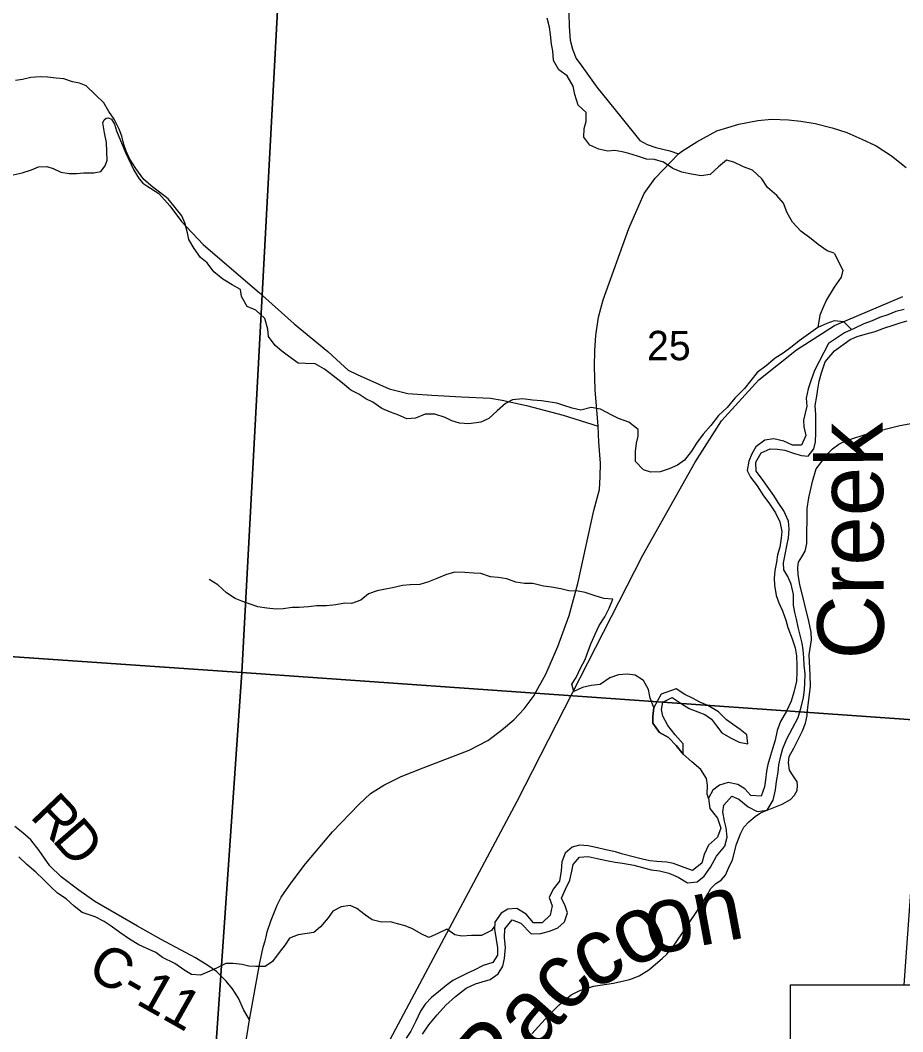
# Model space of a CAD drawing. Extents: x 0 to 34, y 0 to 22.
# Drawn here: x 27.504 to 28.762, y 18.393 to 19.835 of the extents above; entities that cross this region are included whole.
import ezdxf

# ---------------------------------------------------------------- set-up
doc = ezdxf.new("R2010")
doc.units = 0
for name, color, linetype in [('GM_X_County_Road', 7, 'Continuous'), ('GM_X_County_Road_Text', 7, 'Continuous'), ('GM_X_Major_River', 7, 'Continuous'), ('GM_X_Major_River_Text', 7, 'Continuous'), ('GM_X_Minor_Lake', 7, 'Continuous'), ('GM_X_Minor_River', 7, 'Continuous'), ('GM_X_Rail_Line', 7, 'Continuous'), ('GM_X_Section', 7, 'Continuous'), ('GM_X_Section_Text', 7, 'Continuous'), ('GM_X_State_Route', 7, 'Continuous'), ('GM_X_Township_Road', 7, 'Continuous'), ('SH_Data', 7, 'Continuous')]:
    doc.layers.add(name, color=color, linetype=linetype)

msp = doc.modelspace()

# ---------------------------------------------------------------- linework, layer by layer
at = {"layer": 'GM_X_County_Road'}
msp.add_lwpolyline([(27.831, 18.4095), (27.8225, 18.4242), (27.8154, 18.4407), (27.8069, 18.4538), (27.798, 18.4648), (27.7842, 18.4786), (27.772, 18.4872), (27.7543, 18.4979), (27.7053, 18.5242), (27.6717, 18.5432), (27.6108, 18.5786), (27.5882, 18.5945), (27.5628, 18.6135), (27.5466, 18.6294), (27.5316, 18.6511), (27.5197, 18.6661), (27.5083, 18.6765), (27.4967, 18.6851)], dxfattribs=at)
at = {"layer": 'GM_X_Major_River'}
for points in [[(28.7645, 19.4226), (28.7523, 19.4196), (28.741, 19.415), (28.7292, 19.4109), (28.7186, 19.4063), (28.7068, 19.4018), (28.6928, 19.3953), (28.6791, 19.3889), (28.6648, 19.3794)], [(28.6648, 19.3636), (28.6874, 19.3798), (28.6973, 19.384), (28.7087, 19.387), (28.7231, 19.3908), (28.7353, 19.3957), (28.7485, 19.4002), (28.7584, 19.4033), (28.7687, 19.4063)], [(28.6648, 19.3794), (28.6564, 19.3737), (28.6499, 19.3613), (28.643, 19.3484), (28.6365, 19.3352), (28.6314, 19.3208), (28.6276, 19.3091), (28.6248, 19.2958), (28.6255, 19.2844), (28.6232, 19.2746), (28.6208, 19.2644), (28.6215, 19.2549), (28.6241, 19.2427), (28.6179, 19.2291), (28.605, 19.2288), (28.5929, 19.2346), (28.5785, 19.2381), (28.5656, 19.236), (28.553, 19.2266), (28.5473, 19.2167), (28.543, 19.2062), (28.5407, 19.1929), (28.5452, 19.1834), (28.5546, 19.1712), (28.564, 19.1567), (28.5715, 19.1468), (28.5809, 19.1327), (28.5872, 19.1197), (28.5898, 19.106), (28.589, 19.0962), (28.587, 19.0837), (28.5839, 19.0727), (28.5823, 19.0621), (28.5799, 19.0504), (28.5791, 19.0394), (28.5794, 19.0295), (28.582, 19.0147), (28.5857, 19.0044), (28.5909, 18.9926), (28.5958, 18.9793), (28.5987, 18.969), (28.6047, 18.9531), (28.6088, 18.9401), (28.611, 18.9287), (28.6113, 18.9155), (28.6112, 18.9056), (28.6108, 18.8923), (28.6069, 18.8768), (28.603, 18.8639), (28.5964, 18.8496), (28.588, 18.8352), (28.5834, 18.822), (28.5802, 18.8083), (28.5767, 18.7962), (28.574, 18.7864), (28.5701, 18.7735), (28.5682, 18.764), (28.5666, 18.7519), (28.5654, 18.7417), (28.5604, 18.7284), (28.5456, 18.7293), (28.5373, 18.7392), (28.5271, 18.7454), (28.5135, 18.7481), (28.5013, 18.7444), (28.4918, 18.7369), (28.4856, 18.7256), (28.4874, 18.7111), (28.4983, 18.6974), (28.5028, 18.6829), (28.4981, 18.6701), (28.4852, 18.6588), (28.479, 18.6456), (28.4759, 18.6331), (28.4626, 18.6225), (28.4508, 18.6268), (28.4353, 18.6326), (28.4258, 18.6346), (28.4118, 18.6354), (28.4016, 18.6366), (28.3914, 18.6386), (28.3781, 18.6421), (28.3633, 18.646), (28.3527, 18.6491), (28.3391, 18.6519), (28.3274, 18.655), (28.3141, 18.6578), (28.3016, 18.6586), (28.2913, 18.656), (28.281, 18.6474), (28.2764, 18.6349), (28.2752, 18.622), (28.2732, 18.6076), (28.264, 18.5959), (28.2582, 18.5842), (28.2627, 18.572), (28.2596, 18.5588), (28.2485, 18.5479), (28.236, 18.548), (28.2255, 18.5605), (28.2122, 18.5686)], [(28.2057, 18.5523), (28.2178, 18.5473), (28.2329, 18.5324), (28.2465, 18.5327), (28.2602, 18.5364), (28.2705, 18.5409), (28.28, 18.5495), (28.2843, 18.5624), (28.2809, 18.5723), (28.2757, 18.5833), (28.2815, 18.5962), (28.288, 18.609), (28.2907, 18.6215), (28.2927, 18.631), (28.3015, 18.6416), (28.314, 18.6426), (28.3265, 18.6395), (28.3401, 18.6367), (28.3526, 18.6344), (28.3629, 18.6331), (28.3788, 18.6304), (28.3913, 18.6269), (28.4038, 18.6237), (28.4155, 18.6221), (28.4288, 18.6186), (28.442, 18.6132), (28.4556, 18.6051), (28.4693, 18.6066), (28.4792, 18.6144), (28.4884, 18.6273), (28.4968, 18.6428), (28.5087, 18.6571), (28.5122, 18.67), (28.5104, 18.6833), (28.5082, 18.6931), (28.5056, 18.7064), (28.5072, 18.7159), (28.5186, 18.7287), (28.5285, 18.7245), (28.5421, 18.7134), (28.5549, 18.7068), (28.569, 18.7086), (28.5774, 18.723), (28.5809, 18.7378), (28.5825, 18.7495), (28.5845, 18.7628), (28.5857, 18.7734), (28.5884, 18.7863), (28.5912, 18.7965), (28.5969, 18.8105), (28.6131, 18.8407), (28.6177, 18.8555), (28.6208, 18.8691), (28.6221, 18.8801), (28.6225, 18.8896), (28.623, 18.9028), (28.6219, 18.9154), (28.6212, 18.926), (28.6202, 18.937), (28.6187, 18.9465), (28.6161, 18.9579), (28.6132, 18.9697), (28.6106, 18.9811), (28.6084, 18.9906), (28.6065, 19.0008), (28.6066, 19.016), (28.6033, 19.0308), (28.5985, 19.0419), (28.5928, 19.0514), (28.5922, 19.0613), (28.5949, 19.073), (28.5972, 19.0855), (28.5996, 19.0969), (28.6004, 19.1094), (28.5994, 19.1204), (28.593, 19.1352), (28.5848, 19.1474), (28.5784, 19.1573), (28.5716, 19.1673), (28.5611, 19.1817), (28.5532, 19.192), (28.5529, 19.2046), (28.5606, 19.2182), (28.5735, 19.2238), (28.5837, 19.2233), (28.5944, 19.2217), (28.608, 19.2171), (28.6178, 19.2143), (28.6273, 19.2135), (28.6357, 19.2237), (28.6377, 19.2339), (28.6385, 19.2464), (28.6386, 19.2604), (28.6383, 19.2726), (28.6376, 19.2855), (28.6396, 19.2988), (28.6412, 19.309), (28.6432, 19.32), (28.6463, 19.3321), (28.6517, 19.348), (28.6648, 19.3636)], [(28.2122, 18.5686), (28.1993, 18.5676), (28.1898, 18.5619), (28.181, 18.5491), (28.1802, 18.5389), (28.1827, 18.5241), (28.1846, 18.5123), (28.1845, 18.502), (28.178, 18.4915), (28.1643, 18.487), (28.1513, 18.4803), (28.1418, 18.4762), (28.1316, 18.4709), (28.1209, 18.4657), (28.1114, 18.4586), (28.1007, 18.4495), (28.0908, 18.4417), (28.0816, 18.4319), (28.0751, 18.422), (28.0682, 18.4077), (28.0613, 18.3933), (28.0547, 18.3835)], [(28.0779, 18.3894), (28.0867, 18.4026), (28.0986, 18.4169), (28.1112, 18.4305), (28.1249, 18.4429), (28.1402, 18.4546), (28.1531, 18.4609), (28.1626, 18.4639), (28.1744, 18.4672), (28.1854, 18.4751), (28.1923, 18.4861), (28.1947, 18.497), (28.1959, 18.513), (28.1945, 18.5266), (28.195, 18.5395), (28.2057, 18.5523)]]:
    msp.add_lwpolyline(points, dxfattribs=at)
at = {"layer": 'GM_X_Minor_Lake'}
for points in [[(28.4495, 18.7883), (28.4491, 18.8031), (28.4381, 18.816), (28.4275, 18.8292), (28.4202, 18.8425), (28.4183, 18.8519), (28.4202, 18.8626), (28.4334, 18.8694), (28.4478, 18.8596), (28.458, 18.8535), (28.4702, 18.8487), (28.48, 18.8449), (28.4899, 18.8385), (28.4967, 18.8286), (28.5043, 18.8188), (28.5169, 18.8116), (28.529, 18.8056), (28.5415, 18.8033), (28.5399, 18.8158), (28.5304, 18.8238), (28.521, 18.8302), (28.5111, 18.8374), (28.4997, 18.8487), (28.4845, 18.8578), (28.4732, 18.8627), (28.4637, 18.868), (28.4519, 18.8736), (28.4394, 18.8816), (28.4181, 18.8742), (28.4077, 18.8549)], [(28.4077, 18.8549), (28.4062, 18.842), (28.4063, 18.8326), (28.4158, 18.8193), (28.4283, 18.8122), (28.4393, 18.8008), (28.4495, 18.7883)]]:
    msp.add_lwpolyline(points, dxfattribs=at)
at = {"layer": 'GM_X_Minor_River'}
for points in [[(28.6646, 19.5027), (28.6543, 19.5061), (28.6418, 19.5152), (28.6315, 19.5231), (28.6171, 19.534), (28.6053, 19.5469), (28.5977, 19.5602), (28.5924, 19.5738), (28.5829, 19.5851), (28.5696, 19.5961), (28.5612, 19.6086), (28.5483, 19.6211), (28.5351, 19.6256), (28.5214, 19.6324), (28.5112, 19.6354), (28.4995, 19.6259), (28.4878, 19.6149), (28.4749, 19.6129), (28.4613, 19.6152), (28.4473, 19.6182), (28.4348, 19.6234), (28.4211, 19.6325), (28.4086, 19.6363), (28.3972, 19.6366), (28.3844, 19.6408), (28.3718, 19.6449), (28.3624, 19.6471), (28.3518, 19.649), (28.3419, 19.6479), (28.3291, 19.6509), (28.3165, 19.6569), (28.3078, 19.6679), (28.3081, 19.6804), (28.3111, 19.6906), (28.3111, 19.7031), (28.2997, 19.7137), (28.2951, 19.7289), (28.2924, 19.741), (28.2841, 19.7557), (28.2723, 19.7641), (28.2647, 19.7773), (28.2635, 19.7913), (28.2616, 19.8008), (28.26, 19.8144), (28.2588, 19.825), (28.2554, 19.8379)], [(27.6236, 19.717), (27.6119, 19.7283), (27.5986, 19.7412), (27.5891, 19.7449), (27.5792, 19.7472), (27.5664, 19.7513), (27.5558, 19.7521), (27.5433, 19.7535), (27.5327, 19.7543), (27.5198, 19.7531), (27.5077, 19.7504), (27.4975, 19.7489)], [(28.6647, 19.4064), (28.6539, 19.4026), (28.641, 19.3969), (28.6146, 19.3779), (28.6048, 19.3695), (28.5919, 19.36), (28.5806, 19.3528), (28.5678, 19.3421), (28.5549, 19.3326), (28.5368, 19.3098), (28.5229, 19.2958), (28.5119, 19.2828), (28.4995, 19.2714), (28.4889, 19.257), (28.4776, 19.2445), (28.4682, 19.2319), (28.461, 19.2202), (28.4512, 19.2076), (28.4414, 19.2004), (28.4293, 19.1954), (28.4165, 19.1909), (28.4032, 19.1905), (28.393, 19.1938), (28.3816, 19.2056), (28.3812, 19.22), (28.383, 19.2317), (28.3852, 19.242), (28.3852, 19.2514), (28.3719, 19.262), (28.3572, 19.2669), (28.3477, 19.2718), (28.3314, 19.2805), (28.3181, 19.2827), (28.3034, 19.2789), (28.2912, 19.2815), (28.2791, 19.2853), (28.2693, 19.2887), (28.2568, 19.2906), (28.2473, 19.2924), (28.2348, 19.2932), (28.2208, 19.295), (28.206, 19.2938), (28.1962, 19.2885), (28.1841, 19.2779), (28.1724, 19.2668), (28.1607, 19.2619), (28.1437, 19.2596), (28.1304, 19.2603), (28.1198, 19.2637), (28.11, 19.2682), (28.0952, 19.2731), (28.0816, 19.2731), (28.068, 19.2673), (28.0555, 19.2666), (28.0426, 19.2722), (28.0323, 19.276), (28.0198, 19.2813), (28.0069, 19.2903), (27.9971, 19.2948), (27.9872, 19.3016), (27.9755, 19.3073), (27.9637, 19.3175), (27.9504, 19.3277), (27.9379, 19.3372), (27.925, 19.3451), (27.911, 19.3454), (27.9004, 19.3458), (27.8867, 19.356), (27.8772, 19.3632), (27.8677, 19.3711), (27.8582, 19.384), (27.8575, 19.3942), (27.8529, 19.4094), (27.8403, 19.4215), (27.8278, 19.4267), (27.8198, 19.4411), (27.8183, 19.451), (27.8065, 19.4574), (27.7933, 19.4657), (27.7804, 19.4763), (27.7708, 19.4888), (27.7614, 19.4967), (27.7522, 19.5092), (27.745, 19.5224), (27.7431, 19.5319), (27.7389, 19.5459), (27.7347, 19.5558), (27.7252, 19.5679), (27.7153, 19.58), (27.7031, 19.5898), (27.6933, 19.5966), (27.6804, 19.6079), (27.6693, 19.6235), (27.6606, 19.6367), (27.6553, 19.6481), (27.6522, 19.6575), (27.6491, 19.6697), (27.6457, 19.6795), (27.6385, 19.6939), (27.6309, 19.7049), (27.6236, 19.717)], [(28.6646, 19.5027), (28.677, 19.4785), (28.6743, 19.4683), (28.6647, 19.454)], [(28.6647, 19.454), (28.6535, 19.4364), (28.6494, 19.4266), (28.6441, 19.4144), (28.641, 19.3969)], [(28.6894, 19.3938), (28.6785, 19.4046), (28.6647, 19.4064)], [(28.4858, 18.7242), (28.4834, 18.7315), (28.4838, 18.7444), (28.4826, 18.7539), (28.4746, 18.7668), (28.4617, 18.7774), (28.4495, 18.7883), (28.4393, 18.8008), (28.4283, 18.8122), (28.4158, 18.8193), (28.4063, 18.8326), (28.4062, 18.842), (28.4077, 18.8549), (28.4024, 18.8682), (28.3997, 18.8807), (28.3928, 18.8936), (28.3807, 18.9011), (28.3693, 18.9026), (28.3572, 18.9015), (28.3447, 18.8973), (28.3311, 18.8877), (28.3183, 18.8862), (28.3058, 18.8835), (28.2937, 18.8778), (28.2906, 18.8884), (28.297, 18.8979), (28.303, 18.9112), (28.3094, 18.9233), (28.3143, 18.9366), (28.3184, 18.9469), (28.3241, 18.9594), (28.3297, 18.9719), (28.3376, 18.9841), (28.344, 18.9966), (28.3489, 19.0095), (28.336, 19.0106), (28.3239, 19.0144), (28.3095, 19.0189), (28.2997, 19.0207), (28.2864, 19.0211), (28.275, 19.0241), (28.2618, 19.0263), (28.2504, 19.0278), (28.2349, 19.0316), (28.2232, 19.0319), (28.211, 19.0338), (28.1981, 19.0383), (28.1856, 19.0402), (28.1747, 19.0413), (28.161, 19.0458), (28.1508, 19.0465), (28.1379, 19.0476), (28.1239, 19.048), (28.1122, 19.0445), (28.0982, 19.0388), (28.0865, 19.0342), (28.074, 19.0304), (28.06, 19.03), (28.0494, 19.0288), (28.035, 19.0258), (28.0252, 19.0235), (28.0131, 19.0212), (28.001, 19.017), (27.9897, 19.0082), (27.9768, 19.0033), (27.967, 19.0036), (27.9541, 19.0013), (27.9409, 19.0001), (27.9269, 18.9997), (27.9155, 18.9986), (27.9019, 18.9974), (27.892, 18.9974), (27.8792, 18.9958), (27.8693, 18.995), (27.8561, 18.9965), (27.8432, 18.9984), (27.8337, 19.0018), (27.8205, 19.0067), (27.8106, 19.0104), (27.7985, 19.0184), (27.7863, 19.0297), (27.7738, 19.0373)], [(28.1805, 18.5434), (28.1763, 18.537), (28.1619, 18.5298), (28.1476, 18.5301), (28.1339, 18.529), (28.1241, 18.5308), (28.1123, 18.5391), (28.0998, 18.533), (28.087, 18.5273), (28.076, 18.5322), (28.0635, 18.5394), (28.0533, 18.5439), (28.0423, 18.5465), (28.0324, 18.5496), (28.0192, 18.5491), (28.0059, 18.5521), (27.9964, 18.5589), (27.9843, 18.5684), (27.9748, 18.5725), (27.9619, 18.5706), (27.9502, 18.5645), (27.9434, 18.555), (27.9325, 18.5425), (27.9227, 18.5341), (27.9007, 18.531), (27.8883, 18.5261), (27.8819, 18.5166), (27.8736, 18.5056), (27.8641, 18.4927), (27.8536, 18.4858), (27.8403, 18.4858), (27.8305, 18.4861), (27.8206, 18.4888), (27.8078, 18.4899), (27.7975, 18.4902), (27.7851, 18.4837), (27.7749, 18.4792), (27.7616, 18.4734), (27.7484, 18.4742), (27.7389, 18.4802), (27.7249, 18.49), (27.7074, 18.4987), (27.6979, 18.5055), (27.6839, 18.5119), (27.6737, 18.5168), (27.6604, 18.5248), (27.6464, 18.5342), (27.6342, 18.5433), (27.6243, 18.5501), (27.6115, 18.5565), (27.5929, 18.5629), (27.5815, 18.5716), (27.5697, 18.5822), (27.5576, 18.5901), (27.5477, 18.5996), (27.5378, 18.6098), (27.5265, 18.6204), (27.5139, 18.6313), (27.5025, 18.6419)]]:
    msp.add_lwpolyline(points, dxfattribs=at)
at = {"layer": 'GM_X_Rail_Line'}
msp.add_lwpolyline([(27.978, 18.2807), (28.2126, 18.7214), (28.3919, 19.0722), (28.4664, 19.2048), (28.5039, 19.2636), (28.5573, 19.3219), (28.611, 19.3651), (28.6648, 19.3994), (28.7625, 19.4407)], dxfattribs=at)
at = {"layer": 'GM_X_Section'}
for points in [[(27.875, 19.9199), (27.8204, 18.905), (26.8274, 18.9732), (26.893, 19.9764)], [(27.875, 19.9199), (28.8721, 19.8598), (28.7909, 18.8364), (27.8204, 18.905)], [(26.8274, 18.9732), (27.8204, 18.905), (27.7492, 17.8771), (26.7513, 17.9427)]]:
    msp.add_lwpolyline(points, close=True, dxfattribs=at)
msp.add_lwpolyline([(28.7433, 18.1795), (28.7165, 17.8103), (27.7492, 17.8771), (27.8204, 18.905), (28.7909, 18.8364), (28.7636, 18.4595)], dxfattribs=at)
at = {"layer": 'GM_X_State_Route'}
for points in [[(28.3281, 19.2562), (28.3241, 19.3079), (28.3229, 19.3409), (28.3235, 19.3641), (28.3247, 19.3852), (28.3287, 19.4115), (28.3354, 19.436), (28.3718, 19.5379), (28.3868, 19.5715), (28.3935, 19.588), (28.4092, 19.6097), (28.4425, 19.6444), (28.4484, 19.6485), (28.4686, 19.6613), (28.4975, 19.677), (28.5284, 19.6868), (28.5557, 19.6917), (28.5752, 19.6936), (28.5994, 19.6929), (28.6168, 19.6908), (28.6376, 19.6877), (28.6618, 19.6816), (28.6826, 19.6746), (28.704, 19.6654), (28.7242, 19.6556), (28.7462, 19.6413), (28.7673, 19.625)], [(27.8167, 18.318), (27.831, 18.4095), (27.846, 18.4909), (27.8509, 18.5132), (27.8534, 18.5221), (27.8549, 18.5279), (27.8564, 18.5352), (27.8619, 18.552), (27.8708, 18.5731), (27.8763, 18.5845), (27.8904, 18.6052), (27.9109, 18.6322), (27.9495, 18.6777), (27.987, 18.7169), (28.0039, 18.7322), (28.0226, 18.7443), (28.0473, 18.7567), (28.0788, 18.7689), (28.1443, 18.794), (28.1709, 18.808), (28.1904, 18.8227), (28.2079, 18.8374), (28.2226, 18.8533), (28.2369, 18.8723), (28.2375, 18.8734), (28.2535, 18.9026), (28.2706, 18.942), (28.2868, 18.9861), (28.2993, 19.0316), (28.322, 19.1359), (28.3302, 19.1659), (28.3312, 19.1837), (28.3315, 19.2035), (28.3293, 19.2332), (28.3281, 19.2562)]]:
    msp.add_lwpolyline(points, dxfattribs=at)
at = {"layer": 'GM_X_Township_Road'}
for points in [[(28.2862, 19.845), (28.2868, 19.826), (28.2883, 19.8064), (28.2917, 19.7936), (28.297, 19.7802), (28.305, 19.7691), (28.3263, 19.7394), (28.3605, 19.6969), (28.3877, 19.6633), (28.3981, 19.6575), (28.4104, 19.6535), (28.4303, 19.6486), (28.4425, 19.6444)], [(27.4943, 19.6146), (27.5071, 19.6171), (27.5206, 19.6217), (27.5307, 19.6256), (27.5423, 19.6263), (27.5512, 19.6235), (27.5625, 19.6183), (27.5741, 19.6165), (27.5845, 19.6165), (27.5949, 19.6171), (27.6096, 19.6174), (27.6195, 19.619), (27.6255, 19.6272), (27.6285, 19.6351), (27.6273, 19.6605), (27.6246, 19.6743), (27.6224, 19.6887), (27.6243, 19.693), (27.6268, 19.6951), (27.6305, 19.6957), (27.6344, 19.6936), (27.6386, 19.6868), (27.6417, 19.677), (27.6546, 19.6461), (27.6662, 19.6208), (27.6738, 19.6085), (27.679, 19.6027), (27.6851, 19.5987), (27.702, 19.5877), (27.7179, 19.5703), (27.7344, 19.5477), (27.765, 19.5152), (27.8454, 19.4461), (27.895, 19.4021), (27.9427, 19.3626), (27.9607, 19.3461), (27.9717, 19.336), (27.9846, 19.3296), (28.0302, 19.3094), (28.0568, 19.3026), (28.091, 19.3002), (28.1336, 19.2981), (28.1748, 19.2959), (28.1911, 19.2932), (28.2259, 19.2855), (28.2785, 19.2718), (28.3281, 19.2562)], [(28.3729, 18.4674), (28.3756, 18.468), (28.3867, 18.4725), (28.4002, 18.4809), (28.4192, 18.4972), (28.4262, 18.5035), (28.4355, 18.5147), (28.4532, 18.5407), (28.4726, 18.5697), (28.4843, 18.5895), (28.4887, 18.597), (28.4957, 18.6039), (28.5033, 18.6089), (28.5096, 18.6159), (28.5141, 18.6258), (28.5196, 18.638), (28.5254, 18.6599), (28.5309, 18.6751), (28.5358, 18.6846), (28.543, 18.692), (28.5517, 18.6997), (28.5597, 18.7048), (28.5738, 18.7103), (28.5903, 18.7171), (28.6025, 18.7239), (28.6082, 18.7302), (28.612, 18.7367), (28.6124, 18.7437), (28.6118, 18.749), (28.6059, 18.7577), (28.6008, 18.7655), (28.5992, 18.7762), (28.6004, 18.7849), (28.6072, 18.7969), (28.6194, 18.8219), (28.6235, 18.8326), (28.6258, 18.8438), (28.6261, 18.8468), (28.6308, 18.8854), (28.6301, 18.9011), (28.6287, 18.93), (28.6321, 18.9516), (28.6319, 18.9625), (28.6283, 18.9782), (28.6154, 19.0304), (28.6131, 19.044), (28.6127, 19.0549), (28.6135, 19.0624), (28.6186, 19.0696), (28.6232, 19.0779), (28.6254, 19.0889), (28.6259, 19.1387), (28.6285, 19.1541), (28.6336, 19.1774), (28.6389, 19.1951), (28.6467, 19.2057), (28.6551, 19.2167), (28.6621, 19.2238), (28.6712, 19.2306), (28.6823, 19.2354), (28.7147, 19.246), (28.7583, 19.2568), (28.7817, 19.2612)], [(28.2335, 18.3895), (28.2575, 18.4159), (28.2728, 18.4313), (28.2899, 18.4455), (28.3019, 18.4517), (28.3214, 18.4579), (28.3499, 18.4621), (28.3649, 18.4655), (28.3729, 18.4674)]]:
    msp.add_lwpolyline(points, dxfattribs=at)
at = {"layer": 'SH_Data'}
msp.add_lwpolyline([(28.6022, 18.4595), (29.9232, 18.4595), (29.9232, 18.1795), (28.6022, 18.1795)], close=True, dxfattribs=at)

# ---------------------------------------------------------------- texts
at = {"layer": 'GM_X_County_Road_Text'}
for s, height, rotation, p in [('R', 0.0568, 313.6254, (27.5169, 18.6989)), ('D', 0.0568, 310.968, (27.5486, 18.6656)), ('C-11', 0.05682, 330.5374, (27.5977, 18.4729))]:
    msp.add_text(s, height=height, rotation=rotation, dxfattribs=at).set_placement(p)
at = {"layer": 'GM_X_Major_River_Text'}
for s, height, rotation, p in [('Creek', 0.09469, 90.2869, (28.7354, 18.9238)), ('on', 0.09469, 10.5706, (28.4015, 18.5015)), ('co', 0.0947, 28.5715, (28.318, 18.4499)), ('Rac', 0.0947, 48.5724, (28.1778, 18.2931))]:
    msp.add_text(s, height=height, rotation=rotation, dxfattribs=at).set_placement(p)
at = {"layer": 'GM_X_Section_Text'}
msp.add_text('25', height=0.04186, rotation=0, dxfattribs=at).set_placement((28.3977, 19.3501))

doc.saveas('drawing.dxf')
